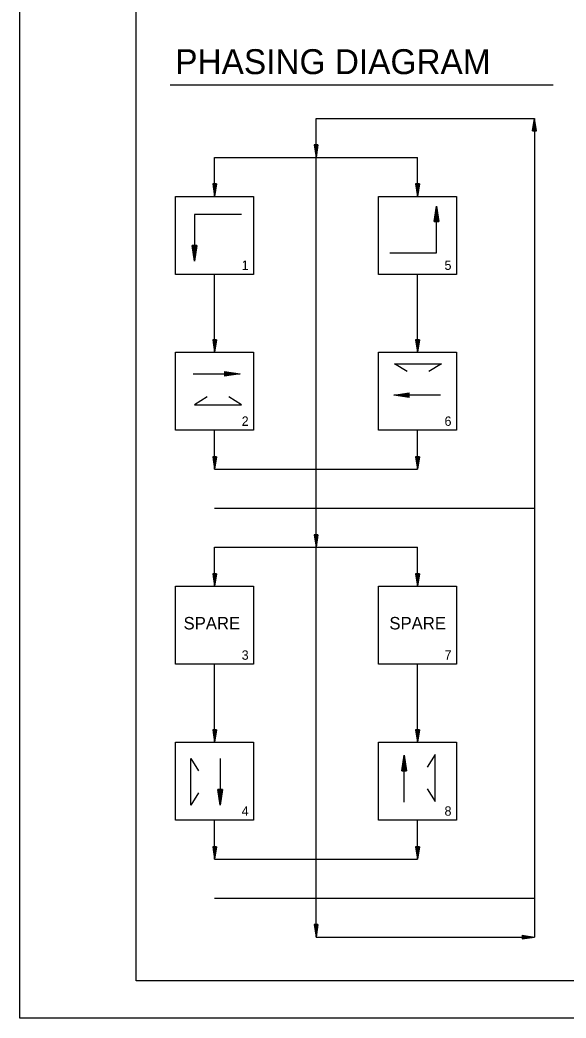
# Model space of a CAD drawing. Extents: x 1281646 to 1282646, y 1891886 to 1892526.
# Drawn here: x 1281646.2 to 1281821.2, y 1891886.5 to 1892206.5 of the extents above; entities that cross this region are included whole.
import ezdxf

# ---------------------------------------------------------------- set-up
doc = ezdxf.new("R2010")
doc.units = 0
for name, color, linetype in [('R_Border', 7, 'Continuous'), ('R_Draft', 7, 'Continuous'), ('R_No Plot', 7, 'Continuous'), ('T_Drafting', 7, 'Continuous'), ('T_Notes', 7, 'Continuous')]:
    doc.layers.add(name, color=color, linetype=linetype)

msp = doc.modelspace()

# ---------------------------------------------------------------- linework, layer by layer
at = {"layer": 'R_Border'}
for p, q in [((1281683.46, 1891898.41), (1281683.46, 1892514.79)), ((1281683.46, 1891898.41), (1281683.46, 1891898.41)), ((1282632, 1891898.41), (1281683.46, 1891898.41))]:
    msp.add_line(p, q, dxfattribs=at)
at = {"layer": 'R_Draft'}
for p, q in [((1281810.51, 1892170.9), (1281811.11, 1892174.9)), ((1281810.61, 1892170.9), (1281811.11, 1892174.23)), ((1281810.72, 1892170.9), (1281811.11, 1892173.55)), ((1281810.82, 1892170.9), (1281811.11, 1892172.88)), ((1281811.71, 1892170.9), (1281811.11, 1892174.9)), ((1281811.61, 1892170.9), (1281811.11, 1892174.23)), ((1281811.51, 1892170.9), (1281811.11, 1892173.55)), ((1281811.41, 1892170.9), (1281811.11, 1892172.88)), ((1281810.51, 1892170.9), (1281811.71, 1892170.9)), ((1281810.92, 1892170.9), (1281811.11, 1892172.2)), ((1281811.02, 1892170.9), (1281811.11, 1892171.53)), ((1281811.31, 1892170.9), (1281811.11, 1892172.2)), ((1281811.21, 1892170.9), (1281811.11, 1892171.53)), ((1281740.51, 1892166.4), (1281741.11, 1892162.4)), ((1281741.71, 1892166.4), (1281740.51, 1892166.4)), ((1281740.61, 1892166.4), (1281741.11, 1892163.07)), ((1281740.72, 1892166.4), (1281741.11, 1892163.76)), ((1281740.82, 1892166.4), (1281741.11, 1892164.42)), ((1281740.92, 1892166.4), (1281741.11, 1892165.1)), ((1281741.02, 1892166.4), (1281741.11, 1892165.77)), ((1281741.71, 1892166.4), (1281741.11, 1892162.4)), ((1281741.31, 1892166.4), (1281741.11, 1892165.1)), ((1281741.51, 1892166.4), (1281741.11, 1892163.76)), ((1281741.61, 1892166.4), (1281741.11, 1892163.07)), ((1281741.41, 1892166.4), (1281741.11, 1892164.42)), ((1281741.21, 1892166.4), (1281741.11, 1892165.77)), ((1281708.01, 1892153.9), (1281708.61, 1892149.9)), ((1281709.21, 1892153.9), (1281708.01, 1892153.9)), ((1281708.11, 1892153.9), (1281708.61, 1892150.57)), ((1281708.22, 1892153.9), (1281708.61, 1892151.26)), ((1281708.32, 1892153.9), (1281708.61, 1892151.92)), ((1281708.42, 1892153.9), (1281708.61, 1892152.6)), ((1281708.52, 1892153.9), (1281708.61, 1892153.27)), ((1281709.21, 1892153.9), (1281708.61, 1892149.9)), ((1281708.81, 1892153.9), (1281708.61, 1892152.6)), ((1281709.01, 1892153.9), (1281708.61, 1892151.26)), ((1281709.11, 1892153.9), (1281708.61, 1892150.57)), ((1281708.91, 1892153.9), (1281708.61, 1892151.92)), ((1281708.71, 1892153.9), (1281708.61, 1892153.27)), ((1281773.01, 1892153.9), (1281773.61, 1892149.9)), ((1281774.21, 1892153.9), (1281773.01, 1892153.9)), ((1281773.11, 1892153.9), (1281773.61, 1892150.57)), ((1281773.22, 1892153.9), (1281773.61, 1892151.26)), ((1281773.32, 1892153.9), (1281773.61, 1892151.92)), ((1281773.42, 1892153.9), (1281773.61, 1892152.6)), ((1281773.52, 1892153.9), (1281773.61, 1892153.27)), ((1281774.21, 1892153.9), (1281773.61, 1892149.9)), ((1281773.81, 1892153.9), (1281773.61, 1892152.6)), ((1281774.01, 1892153.9), (1281773.61, 1892151.26)), ((1281774.11, 1892153.9), (1281773.61, 1892150.57)), ((1281773.91, 1892153.9), (1281773.61, 1892151.92)), ((1281773.71, 1892153.9), (1281773.61, 1892153.27)), ((1281708.01, 1892103.9), (1281708.61, 1892099.9)), ((1281709.21, 1892103.9), (1281708.01, 1892103.9)), ((1281708.11, 1892103.9), (1281708.61, 1892100.57)), ((1281708.22, 1892103.9), (1281708.61, 1892101.26)), ((1281708.32, 1892103.9), (1281708.61, 1892101.92)), ((1281708.42, 1892103.9), (1281708.61, 1892102.6)), ((1281708.52, 1892103.9), (1281708.61, 1892103.27)), ((1281709.21, 1892103.9), (1281708.61, 1892099.9)), ((1281708.81, 1892103.9), (1281708.61, 1892102.6)), ((1281709.01, 1892103.9), (1281708.61, 1892101.26)), ((1281709.11, 1892103.9), (1281708.61, 1892100.57)), ((1281708.91, 1892103.9), (1281708.61, 1892101.92)), ((1281708.71, 1892103.9), (1281708.61, 1892103.27)), ((1281773.01, 1892103.9), (1281773.61, 1892099.9)), ((1281774.21, 1892103.9), (1281773.01, 1892103.9)), ((1281773.11, 1892103.9), (1281773.61, 1892100.57)), ((1281773.22, 1892103.9), (1281773.61, 1892101.26)), ((1281773.32, 1892103.9), (1281773.61, 1892101.92)), ((1281773.42, 1892103.9), (1281773.61, 1892102.6)), ((1281773.52, 1892103.9), (1281773.61, 1892103.27)), ((1281774.21, 1892103.9), (1281773.61, 1892099.9)), ((1281773.81, 1892103.9), (1281773.61, 1892102.6)), ((1281774.01, 1892103.9), (1281773.61, 1892101.26)), ((1281774.11, 1892103.9), (1281773.61, 1892100.57)), ((1281773.91, 1892103.9), (1281773.61, 1892101.92)), ((1281773.71, 1892103.9), (1281773.61, 1892103.27)), ((1281708.01, 1892066.4), (1281708.61, 1892062.4)), ((1281709.21, 1892066.4), (1281708.01, 1892066.4)), ((1281708.11, 1892066.4), (1281708.61, 1892063.07)), ((1281708.22, 1892066.4), (1281708.61, 1892063.76)), ((1281708.32, 1892066.4), (1281708.61, 1892064.42)), ((1281708.42, 1892066.4), (1281708.61, 1892065.1)), ((1281708.52, 1892066.4), (1281708.61, 1892065.77)), ((1281709.21, 1892066.4), (1281708.61, 1892062.4)), ((1281708.81, 1892066.4), (1281708.61, 1892065.1)), ((1281709.01, 1892066.4), (1281708.61, 1892063.76)), ((1281709.11, 1892066.4), (1281708.61, 1892063.07)), ((1281708.91, 1892066.4), (1281708.61, 1892064.42)), ((1281708.71, 1892066.4), (1281708.61, 1892065.77)), ((1281773.01, 1892066.4), (1281773.61, 1892062.4)), ((1281774.21, 1892066.4), (1281773.01, 1892066.4)), ((1281773.11, 1892066.4), (1281773.61, 1892063.07)), ((1281773.22, 1892066.4), (1281773.61, 1892063.76)), ((1281773.32, 1892066.4), (1281773.61, 1892064.42)), ((1281773.42, 1892066.4), (1281773.61, 1892065.1)), ((1281773.52, 1892066.4), (1281773.61, 1892065.77)), ((1281774.21, 1892066.4), (1281773.61, 1892062.4)), ((1281773.81, 1892066.4), (1281773.61, 1892065.1)), ((1281774.01, 1892066.4), (1281773.61, 1892063.76)), ((1281774.11, 1892066.4), (1281773.61, 1892063.07)), ((1281773.91, 1892066.4), (1281773.61, 1892064.42)), ((1281773.71, 1892066.4), (1281773.61, 1892065.77)), ((1281740.51, 1892041.4), (1281741.11, 1892037.4)), ((1281741.71, 1892041.4), (1281740.51, 1892041.4)), ((1281740.61, 1892041.4), (1281741.11, 1892038.07)), ((1281740.72, 1892041.4), (1281741.11, 1892038.76)), ((1281740.82, 1892041.4), (1281741.11, 1892039.42)), ((1281740.92, 1892041.4), (1281741.11, 1892040.1)), ((1281741.02, 1892041.4), (1281741.11, 1892040.77)), ((1281741.71, 1892041.4), (1281741.11, 1892037.4)), ((1281741.31, 1892041.4), (1281741.11, 1892040.1)), ((1281741.51, 1892041.4), (1281741.11, 1892038.76)), ((1281741.61, 1892041.4), (1281741.11, 1892038.07)), ((1281741.41, 1892041.4), (1281741.11, 1892039.42)), ((1281741.21, 1892041.4), (1281741.11, 1892040.77)), ((1281708.01, 1892028.9), (1281708.61, 1892024.9)), ((1281709.21, 1892028.9), (1281708.01, 1892028.9)), ((1281708.11, 1892028.9), (1281708.61, 1892025.57)), ((1281708.22, 1892028.9), (1281708.61, 1892026.26)), ((1281708.32, 1892028.9), (1281708.61, 1892026.92)), ((1281708.42, 1892028.9), (1281708.61, 1892027.6)), ((1281708.52, 1892028.9), (1281708.61, 1892028.27)), ((1281709.21, 1892028.9), (1281708.61, 1892024.9)), ((1281708.81, 1892028.9), (1281708.61, 1892027.6)), ((1281709.01, 1892028.9), (1281708.61, 1892026.26)), ((1281709.11, 1892028.9), (1281708.61, 1892025.57)), ((1281708.91, 1892028.9), (1281708.61, 1892026.92)), ((1281708.71, 1892028.9), (1281708.61, 1892028.27)), ((1281773.01, 1892028.9), (1281773.61, 1892024.9)), ((1281774.21, 1892028.9), (1281773.01, 1892028.9)), ((1281773.11, 1892028.9), (1281773.61, 1892025.57)), ((1281773.22, 1892028.9), (1281773.61, 1892026.26)), ((1281773.32, 1892028.9), (1281773.61, 1892026.92)), ((1281773.42, 1892028.9), (1281773.61, 1892027.6)), ((1281773.52, 1892028.9), (1281773.61, 1892028.27)), ((1281774.21, 1892028.9), (1281773.61, 1892024.9)), ((1281773.81, 1892028.9), (1281773.61, 1892027.6)), ((1281774.01, 1892028.9), (1281773.61, 1892026.26)), ((1281774.11, 1892028.9), (1281773.61, 1892025.57)), ((1281773.91, 1892028.9), (1281773.61, 1892026.92)), ((1281773.71, 1892028.9), (1281773.61, 1892028.27)), ((1281708.01, 1891978.9), (1281708.61, 1891974.9)), ((1281709.21, 1891978.9), (1281708.01, 1891978.9)), ((1281708.11, 1891978.9), (1281708.61, 1891975.57)), ((1281708.22, 1891978.9), (1281708.61, 1891976.26)), ((1281708.32, 1891978.9), (1281708.61, 1891976.92)), ((1281708.42, 1891978.9), (1281708.61, 1891977.6)), ((1281708.52, 1891978.9), (1281708.61, 1891978.27)), ((1281709.21, 1891978.9), (1281708.61, 1891974.9)), ((1281708.81, 1891978.9), (1281708.61, 1891977.6)), ((1281709.01, 1891978.9), (1281708.61, 1891976.26)), ((1281709.11, 1891978.9), (1281708.61, 1891975.57)), ((1281708.91, 1891978.9), (1281708.61, 1891976.92)), ((1281708.71, 1891978.9), (1281708.61, 1891978.27)), ((1281773.01, 1891978.9), (1281773.61, 1891974.9)), ((1281774.21, 1891978.9), (1281773.01, 1891978.9)), ((1281773.11, 1891978.9), (1281773.61, 1891975.57)), ((1281773.22, 1891978.9), (1281773.61, 1891976.26)), ((1281773.32, 1891978.9), (1281773.61, 1891976.92)), ((1281773.42, 1891978.9), (1281773.61, 1891977.6)), ((1281773.52, 1891978.9), (1281773.61, 1891978.27)), ((1281774.21, 1891978.9), (1281773.61, 1891974.9)), ((1281773.81, 1891978.9), (1281773.61, 1891977.6)), ((1281774.01, 1891978.9), (1281773.61, 1891976.26)), ((1281774.11, 1891978.9), (1281773.61, 1891975.57)), ((1281773.91, 1891978.9), (1281773.61, 1891976.92)), ((1281773.71, 1891978.9), (1281773.61, 1891978.27)), ((1281708.01, 1891941.4), (1281708.61, 1891937.4)), ((1281709.21, 1891941.4), (1281708.01, 1891941.4)), ((1281708.11, 1891941.4), (1281708.61, 1891938.07)), ((1281708.22, 1891941.4), (1281708.61, 1891938.76)), ((1281708.32, 1891941.4), (1281708.61, 1891939.42)), ((1281708.42, 1891941.4), (1281708.61, 1891940.1)), ((1281708.52, 1891941.4), (1281708.61, 1891940.77)), ((1281709.21, 1891941.4), (1281708.61, 1891937.4)), ((1281708.81, 1891941.4), (1281708.61, 1891940.1)), ((1281709.01, 1891941.4), (1281708.61, 1891938.76)), ((1281709.11, 1891941.4), (1281708.61, 1891938.07)), ((1281708.91, 1891941.4), (1281708.61, 1891939.42)), ((1281708.71, 1891941.4), (1281708.61, 1891940.77)), ((1281773.01, 1891941.4), (1281773.61, 1891937.4)), ((1281774.21, 1891941.4), (1281773.01, 1891941.4)), ((1281773.11, 1891941.4), (1281773.61, 1891938.07)), ((1281773.22, 1891941.4), (1281773.61, 1891938.76)), ((1281773.32, 1891941.4), (1281773.61, 1891939.42)), ((1281773.42, 1891941.4), (1281773.61, 1891940.1)), ((1281773.52, 1891941.4), (1281773.61, 1891940.77)), ((1281774.21, 1891941.4), (1281773.61, 1891937.4)), ((1281773.81, 1891941.4), (1281773.61, 1891940.1)), ((1281774.01, 1891941.4), (1281773.61, 1891938.76)), ((1281774.11, 1891941.4), (1281773.61, 1891938.07)), ((1281773.91, 1891941.4), (1281773.61, 1891939.42)), ((1281773.71, 1891941.4), (1281773.61, 1891940.77)), ((1281740.51, 1891916.4), (1281741.11, 1891912.4)), ((1281741.71, 1891916.4), (1281740.51, 1891916.4)), ((1281740.61, 1891916.4), (1281741.11, 1891913.07)), ((1281740.72, 1891916.4), (1281741.11, 1891913.76)), ((1281740.82, 1891916.4), (1281741.11, 1891914.42)), ((1281740.92, 1891916.4), (1281741.11, 1891915.1)), ((1281741.02, 1891916.4), (1281741.11, 1891915.77)), ((1281741.71, 1891916.4), (1281741.11, 1891912.4)), ((1281741.31, 1891916.4), (1281741.11, 1891915.1)), ((1281741.51, 1891916.4), (1281741.11, 1891913.76)), ((1281741.61, 1891916.4), (1281741.11, 1891913.07)), ((1281741.41, 1891916.4), (1281741.11, 1891914.42)), ((1281741.21, 1891916.4), (1281741.11, 1891915.77)), ((1281807.11, 1891913), (1281811.11, 1891912.4)), ((1281807.11, 1891913), (1281807.11, 1891911.8)), ((1281807.11, 1891912.9), (1281810.45, 1891912.4)), ((1281807.11, 1891912.8), (1281809.76, 1891912.4)), ((1281807.11, 1891912.7), (1281809.09, 1891912.4)), ((1281807.11, 1891912.6), (1281808.41, 1891912.4)), ((1281807.11, 1891912.5), (1281807.75, 1891912.4)), ((1281807.11, 1891911.8), (1281811.11, 1891912.4)), ((1281807.11, 1891912.21), (1281808.41, 1891912.4)), ((1281807.11, 1891912), (1281809.76, 1891912.4)), ((1281807.11, 1891911.9), (1281810.45, 1891912.4)), ((1281807.11, 1891912.1), (1281809.09, 1891912.4)), ((1281807.11, 1891912.31), (1281807.75, 1891912.4))]:
    msp.add_line(p, q, dxfattribs=at)
at = {"layer": 'R_No Plot'}
msp.add_line((1281646.26, 1891886.47), (1282646.26, 1891886.47), dxfattribs=at)
msp.add_lwpolyline([(1281646.24, 1892526.47), (1282646.26, 1892526.47), (1282646.26, 1891886.46), (1281646.24, 1891886.46)], close=True, dxfattribs=at)
at = {"layer": 'T_Drafting'}
for p, q in [((1281741.11, 1891912.4), (1281741.11, 1892174.9)), ((1281741.11, 1892174.9), (1281811.11, 1892174.9)), ((1281811.11, 1892174.9), (1281811.11, 1891912.4)), ((1281708.61, 1892149.9), (1281708.61, 1892162.4)), ((1281708.61, 1892162.4), (1281773.61, 1892162.4)), ((1281773.61, 1892149.9), (1281773.61, 1892162.4)), ((1281778.98, 1892141.8), (1281779.73, 1892146.8)), ((1281779.73, 1892131.8), (1281779.73, 1892146.8)), ((1281779.73, 1892146.8), (1281780.48, 1892141.8)), ((1281717.17, 1892144.14), (1281702.17, 1892144.14)), ((1281702.17, 1892144.14), (1281702.17, 1892129.14)), ((1281779.73, 1892145.97), (1281779.1, 1892141.8)), ((1281779.23, 1892141.8), (1281779.73, 1892145.11)), ((1281779.73, 1892144.28), (1281779.36, 1892141.8)), ((1281780.35, 1892141.8), (1281779.73, 1892145.97)), ((1281779.73, 1892145.11), (1281780.23, 1892141.8)), ((1281780.1, 1892141.8), (1281779.73, 1892144.28)), ((1281778.98, 1892141.8), (1281780.48, 1892141.8)), ((1281779.49, 1892141.8), (1281779.73, 1892143.43)), ((1281779.73, 1892142.59), (1281779.61, 1892141.8)), ((1281779.73, 1892143.43), (1281779.97, 1892141.8)), ((1281779.85, 1892141.8), (1281779.73, 1892142.59)), ((1281702.17, 1892129.14), (1281701.42, 1892134.14)), ((1281702.92, 1892134.14), (1281701.42, 1892134.14)), ((1281701.55, 1892134.14), (1281702.17, 1892129.98)), ((1281702.17, 1892130.84), (1281701.68, 1892134.14)), ((1281701.8, 1892134.14), (1281702.17, 1892131.67)), ((1281702.17, 1892132.52), (1281701.93, 1892134.14)), ((1281702.06, 1892134.14), (1281702.17, 1892133.35)), ((1281702.17, 1892133.35), (1281702.29, 1892134.14)), ((1281702.42, 1892134.14), (1281702.17, 1892132.52)), ((1281702.17, 1892131.67), (1281702.55, 1892134.14)), ((1281702.67, 1892134.14), (1281702.17, 1892130.84)), ((1281702.17, 1892129.98), (1281702.8, 1892134.14)), ((1281702.92, 1892134.14), (1281702.17, 1892129.14)), ((1281764.73, 1892131.8), (1281779.73, 1892131.8)), ((1281708.61, 1892099.9), (1281708.61, 1892124.9)), ((1281773.61, 1892099.9), (1281773.61, 1892124.9)), ((1281701.76, 1892093), (1281716.76, 1892093)), ((1281711.76, 1892093.75), (1281716.76, 1892093)), ((1281711.76, 1892093.75), (1281711.76, 1892092.25)), ((1281715.93, 1892093), (1281711.76, 1892093.63)), ((1281711.76, 1892093.5), (1281715.07, 1892093)), ((1281714.23, 1892093), (1281711.76, 1892093.37)), ((1281711.76, 1892093.24), (1281713.39, 1892093)), ((1281712.55, 1892093), (1281711.76, 1892093.12)), ((1281716.76, 1892093), (1281711.76, 1892092.25)), ((1281711.76, 1892092.38), (1281715.93, 1892093)), ((1281715.07, 1892093), (1281711.76, 1892092.5)), ((1281711.76, 1892092.63), (1281714.23, 1892093)), ((1281713.39, 1892093), (1281711.76, 1892092.76)), ((1281711.76, 1892092.88), (1281712.55, 1892093)), ((1281765.99, 1892086.19), (1281770.99, 1892086.94)), ((1281780.99, 1892086.19), (1281765.99, 1892086.19)), ((1281770.99, 1892085.44), (1281765.99, 1892086.19)), ((1281770.99, 1892086.81), (1281766.82, 1892086.19)), ((1281766.82, 1892086.19), (1281770.99, 1892085.56)), ((1281767.68, 1892086.19), (1281770.99, 1892086.69)), ((1281770.99, 1892085.69), (1281767.68, 1892086.19)), ((1281770.99, 1892086.56), (1281768.51, 1892086.19)), ((1281768.51, 1892086.19), (1281770.99, 1892085.82)), ((1281769.36, 1892086.19), (1281770.99, 1892086.43)), ((1281770.99, 1892085.95), (1281769.36, 1892086.19)), ((1281770.99, 1892086.31), (1281770.2, 1892086.19)), ((1281770.2, 1892086.19), (1281770.99, 1892086.07)), ((1281770.99, 1892085.44), (1281770.99, 1892086.94)), ((1281708.61, 1892062.4), (1281708.61, 1892074.9)), ((1281773.61, 1892062.4), (1281773.61, 1892074.9)), ((1281708.61, 1892062.4), (1281773.61, 1892062.4)), ((1281708.61, 1892049.9), (1281811.11, 1892049.9)), ((1281708.61, 1892037.4), (1281773.61, 1892037.4)), ((1281708.61, 1892024.9), (1281708.61, 1892037.4)), ((1281773.61, 1892024.9), (1281773.61, 1892037.4)), ((1281708.61, 1891974.9), (1281708.61, 1891999.9)), ((1281773.61, 1891974.9), (1281773.61, 1891999.9)), ((1281768.57, 1891965.71), (1281769.32, 1891970.71)), ((1281769.32, 1891955.71), (1281769.32, 1891970.71)), ((1281769.32, 1891970.71), (1281770.07, 1891965.71)), ((1281710.42, 1891969.68), (1281710.42, 1891954.68)), ((1281769.32, 1891969.88), (1281768.7, 1891965.71)), ((1281768.83, 1891965.71), (1281769.32, 1891969.02)), ((1281769.32, 1891968.19), (1281768.95, 1891965.71)), ((1281769.95, 1891965.71), (1281769.32, 1891969.88)), ((1281769.32, 1891969.02), (1281769.82, 1891965.71)), ((1281769.7, 1891965.71), (1281769.32, 1891968.19)), ((1281768.57, 1891965.71), (1281770.07, 1891965.71)), ((1281769.08, 1891965.71), (1281769.32, 1891967.34)), ((1281769.32, 1891966.5), (1281769.21, 1891965.71)), ((1281769.32, 1891967.34), (1281769.57, 1891965.71)), ((1281769.44, 1891965.71), (1281769.32, 1891966.5)), ((1281710.42, 1891954.68), (1281709.67, 1891959.68)), ((1281711.17, 1891959.68), (1281709.67, 1891959.68)), ((1281709.79, 1891959.68), (1281710.42, 1891955.51)), ((1281710.42, 1891956.37), (1281709.92, 1891959.68)), ((1281710.04, 1891959.68), (1281710.42, 1891957.21)), ((1281710.42, 1891958.05), (1281710.17, 1891959.68)), ((1281710.3, 1891959.68), (1281710.42, 1891958.89)), ((1281710.42, 1891958.89), (1281710.53, 1891959.68)), ((1281710.66, 1891959.68), (1281710.42, 1891958.05)), ((1281710.42, 1891957.21), (1281710.79, 1891959.68)), ((1281710.91, 1891959.68), (1281710.42, 1891956.37)), ((1281710.42, 1891955.51), (1281711.04, 1891959.68)), ((1281711.17, 1891959.68), (1281710.42, 1891954.68)), ((1281708.61, 1891937.4), (1281708.61, 1891949.9)), ((1281773.61, 1891937.4), (1281773.61, 1891949.9)), ((1281708.61, 1891937.4), (1281773.61, 1891937.4)), ((1281708.61, 1891924.9), (1281811.11, 1891924.9)), ((1281741.11, 1891912.4), (1281811.11, 1891912.4))]:
    msp.add_line(p, q, dxfattribs=at)
for points in [[(1281696.11, 1892149.9), (1281721.11, 1892149.9), (1281721.11, 1892124.9), (1281696.11, 1892124.9)], [(1281761.11, 1892149.9), (1281786.11, 1892149.9), (1281786.11, 1892124.9), (1281761.11, 1892124.9)], [(1281696.11, 1892099.9), (1281721.11, 1892099.9), (1281721.11, 1892074.9), (1281696.11, 1892074.9)], [(1281761.11, 1892099.9), (1281786.11, 1892099.9), (1281786.11, 1892074.9), (1281761.11, 1892074.9)], [(1281696.11, 1892024.9), (1281721.11, 1892024.9), (1281721.11, 1891999.9), (1281696.11, 1891999.9)], [(1281761.11, 1892024.9), (1281786.11, 1892024.9), (1281786.11, 1891999.9), (1281761.11, 1891999.9)], [(1281696.11, 1891974.9), (1281721.11, 1891974.9), (1281721.11, 1891949.9), (1281696.11, 1891949.9)], [(1281761.11, 1891974.9), (1281786.11, 1891974.9), (1281786.11, 1891949.9), (1281761.11, 1891949.9)]]:
    msp.add_lwpolyline(points, close=True, dxfattribs=at)
for points in [[(1281770.28, 1892093.72), (1281766.28, 1892096.22), (1281781.28, 1892096.22), (1281777.28, 1892093.72)], [(1281706.17, 1892085.6), (1281702.17, 1892083.1), (1281717.17, 1892083.1), (1281713.17, 1892085.6)], [(1281776.73, 1891959.92), (1281779.23, 1891955.92), (1281779.23, 1891970.92), (1281776.73, 1891966.92)], [(1281703.44, 1891958.68), (1281700.94, 1891954.68), (1281700.94, 1891969.68), (1281703.44, 1891965.68)]]:
    msp.add_lwpolyline(points, dxfattribs=at)
at = {"layer": 'T_Notes'}
msp.add_line((1281694.39, 1892185.62), (1281817.03, 1892185.62), dxfattribs=at)

# ---------------------------------------------------------------- texts
at = {"layer": 'T_Drafting'}
for p in [(1281698.65, 1892011.05), (1281764.6, 1892011.05)]:
    msp.add_text('SPARE', height=4, dxfattribs=at).set_placement(p)
at = {"layer": 'T_Notes'}
for s, height, p in [('PHASING DIAGRAM', 8, (1281695.99, 1892189.09)), ('1', 3, (1281717.27, 1892126.33)), ('5', 3, (1281782.27, 1892126.33)), ('2', 3, (1281717.27, 1892076.33)), ('6', 3, (1281782.27, 1892076.33)), ('3', 3, (1281717.27, 1892001.33)), ('7', 3, (1281782.27, 1892001.33)), ('4', 3, (1281717.27, 1891951.33)), ('8', 3, (1281782.27, 1891951.33))]:
    msp.add_text(s, height=height, dxfattribs=at).set_placement(p)

doc.saveas('drawing.dxf')
